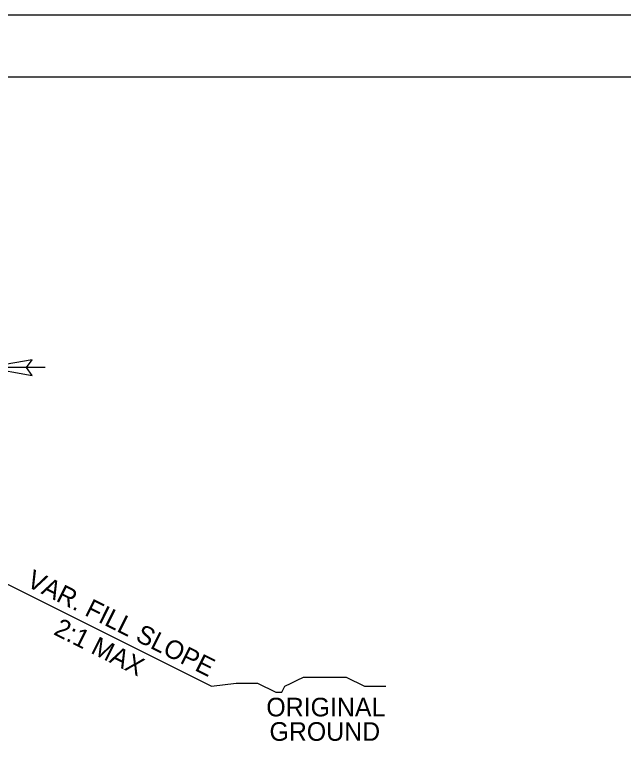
# Model space of a CAD drawing. Extents: x 1487909 to 1489267, y 497866 to 499814.
# Drawn here: x 1489002.61 to 1489027.14, y 497945.93 to 497976.22 of the extents above; entities that cross this region are included whole.
import ezdxf

# ---------------------------------------------------------------- set-up
doc = ezdxf.new("R2010")
doc.units = 0
for name, color, linetype in [('Prop Dimension', 7, 'Continuous'), ('Prop Terminator CELL', 7, 'Continuous'), ('Sheet Plot Border Outside CELL', 7, 'Continuous'), ('Sheet Typical CELL', 7, 'Continuous'), ('Typical Hinge Slope Arterial CELL', 7, 'Continuous')]:
    doc.layers.add(name, color=color, linetype=linetype)

msp = doc.modelspace()

# ---------------------------------------------------------------- linework, layer by layer
at = {"layer": 'Prop Dimension'}
msp.add_line((1489003.828, 497962.026), (1489001.497, 497962.026), dxfattribs=at)
at = {"layer": 'Prop Terminator CELL'}
msp.add_lwpolyline([(1489003.297, 497962.336), (1489001.497, 497962.026), (1489003.307, 497961.706), (1489003.077, 497962.026)], close=True, dxfattribs=at)
at = {"layer": 'Sheet Plot Border Outside CELL'}
msp.add_lwpolyline([(1489051.664, 497976.221), (1488883.264, 497976.221), (1488883.264, 497866.221), (1489051.664, 497866.221)], close=True, dxfattribs=at)
at = {"layer": 'Sheet Typical CELL'}
msp.add_lwpolyline([(1489049.964, 497973.721), (1488899.964, 497973.721), (1488899.964, 497868.721), (1489049.964, 497868.721)], close=True, dxfattribs=at)
at = {"layer": 'Typical Hinge Slope Arterial CELL'}
msp.add_line((1489001.497, 497953.7), (1489010.526, 497949.186), dxfattribs=at)
msp.add_lwpolyline([(1489010.526, 497949.186), (1489011.511, 497949.309), (1489011.758, 497949.309), (1489012.128, 497949.309), (1489012.374, 497949.309), (1489012.621, 497949.186), (1489012.867, 497949.062), (1489013.113, 497948.939), (1489013.36, 497948.939), (1489013.483, 497949.186), (1489013.73, 497949.309), (1489013.976, 497949.432), (1489014.223, 497949.555), (1489014.469, 497949.555), (1489014.715, 497949.555), (1489014.962, 497949.555), (1489015.208, 497949.555), (1489015.454, 497949.555), (1489015.701, 497949.555), (1489015.947, 497949.555), (1489016.193, 497949.432), (1489016.44, 497949.309), (1489016.686, 497949.186), (1489017.056, 497949.186), (1489017.303, 497949.186), (1489017.549, 497949.186)], dxfattribs=at)

# ---------------------------------------------------------------- texts
for s, p in [('VAR. FILL SLOPE', (1489003.029, 497953.231)), ('2:1 MAX', (1489004.126, 497951.286))]:
    msp.add_text(s, height=0.75, rotation=333.4658, dxfattribs=at).set_placement(p)
for s, p in [('ORIGINAL', (1489012.733, 497947.969)), ('GROUND', (1489012.859, 497946.986))]:
    msp.add_text(s, height=0.75, dxfattribs=at).set_placement(p)

doc.saveas('drawing.dxf')
